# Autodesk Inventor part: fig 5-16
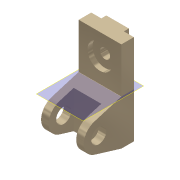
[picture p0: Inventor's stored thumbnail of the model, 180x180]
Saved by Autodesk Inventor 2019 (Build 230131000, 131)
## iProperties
Shininess: 65.0
Angle Display Precision: 2
Document Length Units: 11269
Document Angle Units: 11279
Document Time Units: 11290
Document Mass Units: 11283
Document Length Units Precision: 3
Document Angle Units Precision: 2
Compacted: False
Created: 2001-11
Part Number: fig 5-16
Document SubType Name: Modeling
Designer: Renu Muthoo
Density: 1 g/cm^3
Material: Generic
Appearance: Metal-Titanium (Polished)
Density: 0.0
Volumn: 0.0
Area: 0.0
PropertySet Name: Model Information
Control State: 0
Master: False
Checked Out: False
Author: Renu Muthoo
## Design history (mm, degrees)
node "Sketch1"
sketch "Sketch2"
  geometry: L1 (33.257, 104.664)-(33.257, -75.336); L2 (33.257, -75.336)-(8.257, -75.336); L3 (8.257, -75.336)-(-45.451, -59.045); L4 (-45.451, -1.628)-(8.257, 14.664); L5 (8.257, 14.664)-(8.257, 104.664); L6 (8.257, 104.664)-(33.257, 104.664); C1 r 15 at (-36.743, -30.336); A1 r 30 centre (-36.743, -30.336) between (-45.451, -1.628) and (-45.451, -59.045)
  constraints: 12 end point, 2 centre point, 2 equal length, 2 parallel, 2 point on circle, 2 tangent, 1 coincident, 1 perpendicular, 1 vertical
  dimensions: "d0" = 180 distance of L1.start L1.end; "d1" = 30 radius of A1; "d2" = 25 distance of L5.end L1.start; "d3" = 45 distance from line of L2 A1.centre; "d4" = 70 distance from line of L1 A1.centre; "d5" = 30 diameter of C1
extrude "Extrusion1" new body sketch "Sketch2" distance "d6" = 85; taper "d7" = 0 deg
workplane "Work Plane1"
sketch "Sketch3"
  geometry: L1 (15, 62.364)-(70, 62.364); L2 (70, 62.364)-(70, -52.386); L3 (70, -52.386)-(15, -52.386); L4 (15, -52.386)-(15, 62.364); L5 (0, -45)-(0, -28.708) reference
  constraints: 8 end point, 2 parallel, 1 horizontal, 1 perpendicular
  dimensions: "d8" = 55 distance of L1.start L1.end; "d9" = 15 distance between parallel lines of L5 L4
extrude "Extrusion2" cut sketch "Sketch3" distance "d10" = 50; taper "d11" = 0 deg
sketch "Sketch4"
  geometry: L1 (0, 25)-(85, 25) reference; L2 (0, 0)-(0, 25) reference; L3 (20, 25)-(65, 25); L4 (65, 25)-(65, 35); L5 (65, 35)-(20, 35); L6 (20, 35)-(20, 25)
  constraints: 8 end point, 2 parallel, 1 horizontal, 1 perpendicular, 1 point on line
  dimensions: "d12" = 45 distance of L4.end L5.end; "d13" = 10 distance of L3.end L4.end; "d14" = 20 distance between parallel lines of L2 L6
extrude "Extrusion3" join sketch "Sketch4" stored distance "d15" = 50; taper "d16" = 0 deg
sketch "Sketch5"
  geometry: L1 (85, 0)-(85, 90) reference; L2 (0, 90)-(85, 90) reference; 1 further point
  dimensions: "d17" = 42 distance from line of L2 point (42.5, 48); "d18" = 42.5 distance from line of L1 point (42.5, 48)
hole "Hole1" sketch "Sketch5" at (42.5, 48) diameter "d19" = 20; stored, may be unused: countersink angle "d23" = 82 deg, drill point angle "d25" = 118 deg; dims "d20" = 6, "d21" = 50, "d22" = 10, "d24" = 8
workplane "Work Plane7"
body "Solid1"
other parameters: "d27" = 90 deg
